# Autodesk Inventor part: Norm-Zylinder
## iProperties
Created: 2005-01
Part Number: Norm-Zylinder
Material: 1.0037 St 37-2 / S235JR
Document SubType Name: Modellieren
Designer: mbm
Manufacturer: Standard
Standards Organization: Custom
Density: 1 g/cm^3
Catalog Web Link: www.mittelmeyer.de
Author: mbm
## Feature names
1. Extrusion2
